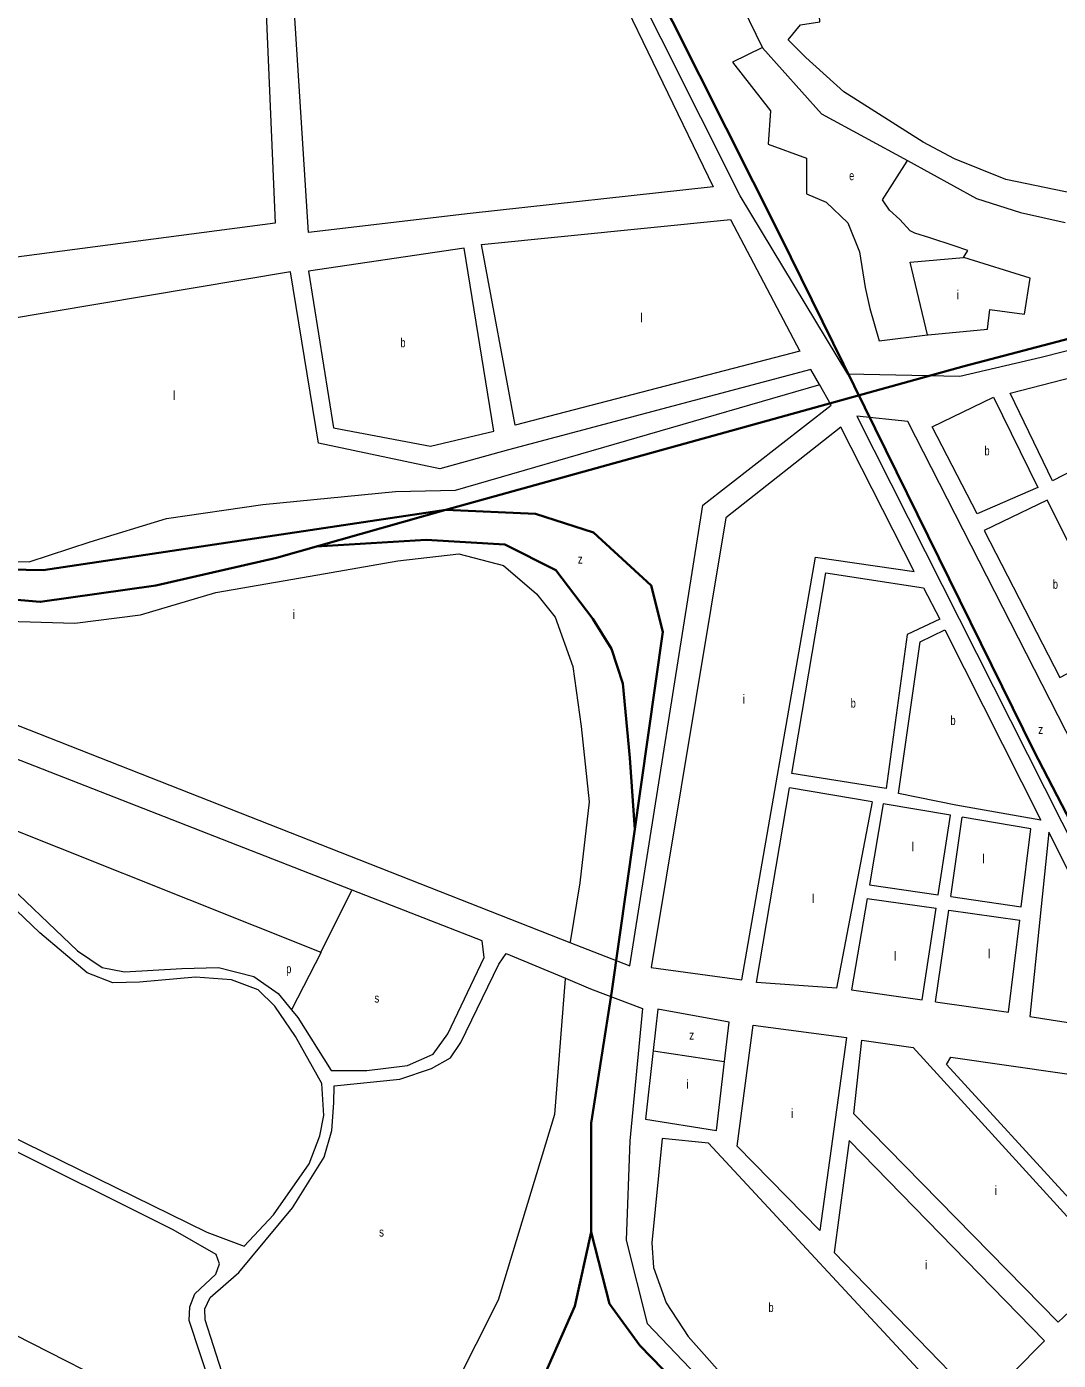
# Model space of a CAD drawing. Extents: x 639657 to 671642, y 222838 to 252123.
# Drawn here: x 654734 to 655866, y 237316 to 238779 of the extents above; entities that cross this region are included whole.
import ezdxf

# ---------------------------------------------------------------- set-up
doc = ezdxf.new("R2010")
doc.units = 0
doc.header["$LTSCALE"] = 4
for name, color, linetype, lineweight in [('1', 7, 'Continuous', 13), ('21', 7, 'Continuous', 13), ('57', 7, 'Continuous', 35)]:
    doc.layers.add(name, color=color, linetype=linetype, lineweight=lineweight)
doc.layers.add('7', color=7, linetype='Continuous')

msp = doc.modelspace()

# ---------------------------------------------------------------- linework, layer by layer
at = {"layer": '1'}
for p, q in [((655573.543, 237959.93), (655610.77, 238179.7)), ((655677.028, 237943.286), (655573.543, 237959.93)), ((655661.614, 237928.754), (655570.866, 237944.123)), ((655734.136, 237826.789), (655747.502, 237914.018)), ((655747.735, 237824.798), (655760.41, 237911.854)), ((655233.82, 237776.3), (655091.058, 237832.008)), ((655658.718, 237837.833), (655734.136, 237826.789)), ((655656.148, 237822.707), (655639.12, 237722.47)), ((655656.148, 237822.707), (655731.866, 237811.973)), ((655747.735, 237824.798), (655825.198, 237813.453)), ((655716.465, 237711.459), (655731.866, 237811.973)), ((655730.933, 237709.399), (655745.585, 237810.028)), ((655745.585, 237810.028), (655823.446, 237798.99)), ((655639.12, 237722.47), (655716.465, 237711.459)), ((655426.45, 237701.43), (655421.307, 237655.861))]:
    msp.add_line(p, q, dxfattribs=at)
for points in [[(655757.79, 238394.89), (655635, 238397.56), (655516.94, 238593.09), (655387.1, 238851.85), (655218.68, 239196.07), (655116.33, 239399.32), (655031.02, 239566.46), (655002.45, 239634.53), (655028.09, 239640.54), (655070.34, 239648.57), (655090.41, 239641.01), (655108.51, 239626.42), (655128.77, 239589.85), (655166.65, 239514.49), (655216.84, 239420.09), (655541.27, 238755.5)], [(656718.907, 238780.019), (656625.27, 238774.66), (656525.23, 238756.25), (656405.61, 238726.41), (656315.33, 238704.82), (656225.69, 238679.49), (656149.4, 238649.6), (656114.03, 238632.12), (656063.82, 238641.61), (656057.49, 238615.66), (655994.43, 238601.74), (655937.14, 238593.33), (655873.63, 238597.66), (655808.27, 238611.08), (655751.82, 238633.86), (655717.51, 238651.81), (655630.69, 238707.14), (655588.91, 238744.79), (655569.62, 238764.19), (655583.18, 238780.65), (655604.36, 238783.92), (655596.58, 238911.02)], [(655541.27, 238755.5), (655605.91, 238683.22), (655700.291, 238631.718)], [(655700.291, 238631.718), (655776.01, 238590.4), (655824.22, 238574.94), (655873.4, 238563.8)], [(655187.53, 238293.76), (655054.44, 238321.79), (655023.58, 238509.9), (654655.16, 238448.15), (654651, 238265.87), (654629.499, 238213.197), (654604.311, 238151.491)], [(655972.49, 238447.52), (655847, 238415.92), (655757.79, 238394.89)], [(655603.686, 238386.179), (655594.24, 238402.65), (655262.68, 238314.59), (655187.53, 238293.76)], [(655330.132, 237774.561), (655395.96, 237748.72), (655475.98, 238254.09), (655616.72, 238363.45), (655603.686, 238386.179)], [(655610.77, 238179.7), (655717.79, 238163.28), (655735.84, 238128.82), (655699.86, 238112.23), (655677.028, 237943.286)], [(654604.311, 238151.491), (654571.94, 238072.19), (655330.132, 237774.561)], [(655091.058, 237832.008), (654562.24, 238038.36), (654553.18, 238035.45), (654512.29, 237952.25), (654512.66, 237937.22), (654526.22, 237910.7), (654538.18, 237905.09), (654607.66, 237897.69)], [(655661.614, 237928.754), (655622.41, 237724.32), (655534.7, 237730.62), (655570.866, 237944.123)], [(655747.502, 237914.018), (655673.76, 237926.38), (655658.718, 237837.833)], [(655825.198, 237813.453), (655835.59, 237899.25), (655760.41, 237911.854)], [(654607.66, 237897.69), (654631.51, 237889.15), (654666.31, 237872.29), (654700.71, 237850.05), (654789.85, 237765.25), (654817.17, 237747.13), (654841.46, 237742.36), (654904.21, 237746.07), (654944.48, 237747.08), (654983.4, 237737.3), (655010.19, 237718.63), (655024.83, 237700.799)], [(654691.45, 237574.71), (654931.87, 237456.7), (654972.69, 237441.44), (655004.99, 237475.71), (655043.95, 237531.63), (655055.6, 237562.57), (655060.12, 237584.7), (655057.78, 237619.91), (655029.1, 237671.3), (655006.24, 237704.57), (654988.07, 237722.38), (654958.78, 237733.47), (654919.5, 237736.53), (654857.86, 237730.95), (654828.87, 237730.23), (654800.66, 237741.35), (654748.53, 237785.17), (654689.1, 237841.7)], [(655730.933, 237709.399), (655811.21, 237697.97), (655823.446, 237798.99)], [(655024.83, 237700.799), (655031.8, 237692.31), (655068.29, 237633.96), (655107.38, 237634.03), (655151.83, 237639.44), (655179.99, 237651.96), (655196.08, 237674.38), (655235.88, 237758.09), (655233.82, 237776.3)], [(655128.869, 237139.406), (654971.76, 237216.77), (654979.59, 237226.1), (654975.91, 237244.28), (654966.71, 237246.73), (654930, 237360.78), (654929.65, 237372.73), (654935.3, 237385.09), (654966.84, 237412.74), (655025.88, 237483.56), (655060.37, 237539.17), (655068.76, 237568.39), (655071.23, 237598.54), (655071.3, 237617.34), (655143.64, 237624.52), (655178.27, 237636.13), (655198.93, 237647.93), (655210.32, 237664.87), (655252.22, 237750.8), (655259.99, 237762.27), (655325.088, 237735.267)], [(655325.088, 237735.267), (655352.83, 237723.76), (655409.78, 237702.09), (655395.78, 237557.04), (655391.93, 237448.21), (655414.69, 237356.56), (655633.75, 237127.48)], [(655499.747, 237644.013), (655504.71, 237687.27), (655426.45, 237701.43)], [(655421.307, 237655.861), (655412.83, 237580.75), (655491.05, 237568.2), (655499.747, 237644.013)]]:
    msp.add_lwpolyline(points, dxfattribs=at)
for points in [[(655321.66, 238945.55), (655487.32, 238603.19), (655220.8, 238573.91), (655043.17, 238552.93), (655001.02, 239218.6), (655171.2, 239246.48)], [(654978.88, 239211.77), (655006.9, 238563.25), (654653.18, 238516.81), (654662.52, 238830.84), (654668.1, 239166.26)], [(655232.94, 238539.82), (655506.31, 238567.03), (655582.19, 238422.66), (655270.2, 238341.86)], [(655177.21, 238318.67), (655246.52, 238335.17), (655214.24, 238535.59), (655043.17, 238510.66), (655070.85, 238338.59)], [(655859.35, 238280.68), (655812.89, 238376.75), (655940.78, 238409.79), (655974.43, 238339.95)], [(655776.9, 238244.6), (655727.34, 238339.7), (655794.74, 238372.54), (655843.42, 238273.3)], [(655644.769, 238351.536), (655981.971, 237684.267), (655999.696, 237676.665), (656047.807, 237666.529), (655700.903, 238345.623)], [(655419.34, 237747.08), (655518.52, 237733.44), (655599.32, 238197.07), (655707.67, 238181.29), (655627.43, 238339.36), (655501, 238240.07)], [(655933.71, 238099.9), (655853.43, 238259.58), (655784.43, 238226.17), (655867.44, 238064.95)], [(655714.44, 238104.11), (655741.18, 238117.34), (655846.64, 237908.66), (655753.37, 237925.17), (655690.41, 237937.78)], [(655834.51, 237693.3), (655949.34, 237675.4), (655959.76, 237688.37), (655855.55, 237895.39)], [(655633.44, 237670.23), (655604.3, 237458.52), (655513.41, 237551.22), (655531.04, 237683.79)], [(655927.63, 237416.82), (655865.71, 237358.16), (655641.45, 237586.63), (655650.17, 237667.42), (655706.78, 237659.16)], [(655747.86, 237648.91), (655994.78, 237613.16), (656001.01, 237600.42), (655881.85, 237489.49), (655743.23, 237640.73)], [(654627.3, 237392.18), (654946.15, 237229.85), (654950.04, 237246.06), (654912.27, 237360.07), (654913.29, 237374.94), (654918.52, 237389.23), (654941.62, 237410.75), (654945.63, 237422.13), (654942.15, 237432.25), (654894.85, 237459.45), (654697.28, 237557.76), (654682.1, 237563.29), (654667.02, 237565.06), (654649.89, 237562.48), (654496.77, 237516.88), (654463.4, 237519.26), (654418.52, 237535.24), (654379.14, 237563.26), (654314.56, 237546.61), (654479.4, 237463.7)], [(655730.21, 237286.76), (655482.26, 237554.55), (655431.09, 237559.72), (655420, 237445.01), (655421.75, 237418.19), (655435.62, 237379.32), (655459.65, 237342.32), (655512.17, 237283.46), (655611.28, 237178.99)], [(655620.01, 237434.63), (655781.57, 237267.83), (655850.73, 237337.77), (655636.27, 237557.5)]]:
    msp.add_lwpolyline(points, close=True, dxfattribs=at)
at = {"layer": '21'}
for points in [[(655541.27, 238755.5), (655540.77, 238755.258), (655508.46, 238739.647), (655550.24, 238686.434), (655547.708, 238649.692), (655589.488, 238634.489), (655589.488, 238595.213), (655611.012, 238586.345), (655635.067, 238563.54), (655647.728, 238531.865), (655654.058, 238492.59), (655659.122, 238469.784), (655669.251, 238434.309), (655722.426, 238440.644)], [(655761.674, 238525.531), (655766.738, 238533.132), (655751.545, 238538.2), (655724.958, 238547.069), (655708.499, 238552.137), (655703.435, 238554.671), (655692.04, 238567.341), (655680.645, 238577.476), (655673.049, 238588.879), (655699.973, 238631.218), (655700.291, 238631.718)], [(655722.426, 238440.644), (655703.435, 238520.463), (655761.674, 238525.531)], [(655722.426, 238440.644), (655722.926, 238440.692), (655788.262, 238446.979), (655790.794, 238468.517), (655828.776, 238463.449), (655835.106, 238502.725), (655762.174, 238525.376), (655761.674, 238525.531)], [(654629.499, 238213.197), (654629.999, 238213.053), (654699.447, 238193.006), (654736.807, 238191.717), (654803.795, 238213.632), (654887.531, 238239.416), (654993.168, 238254.885), (655138.74, 238269.066), (655204.44, 238270.355), (655603.186, 238386.034), (655603.686, 238386.179)], [(654604.311, 238151.491), (654604.811, 238151.351), (654640.187, 238141.439), (654700.735, 238127.259), (654787.047, 238124.68), (654859.189, 238133.704), (654941.637, 238158.198), (655053.714, 238177.536), (655141.315, 238193.006), (655208.304, 238200.741), (655257.258, 238187.849), (655293.328, 238156.909), (655313.94, 238131.126), (655333.264, 238076.981), (655342.282, 238011.234), (655351.3, 237928.728), (655340.994, 237839.776), (655330.215, 237775.061), (655330.132, 237774.561)], [(654607.66, 237897.69), (654607.872, 237898.19), (654624.085, 237936.465), (655056.936, 237763.718)], [(655056.936, 237763.718), (655090.808, 237831.508), (655091.058, 237832.008)], [(655056.936, 237763.718), (655056.681, 237763.218), (655025.085, 237701.299), (655024.83, 237700.799)], [(655325.088, 237735.267), (655325.049, 237734.767), (655313.298, 237585.814), (655251.462, 237382.127), (655129.122, 237139.906), (655128.869, 237139.406)], [(655421.307, 237655.861), (655421.807, 237655.785), (655499.247, 237644.089), (655499.747, 237644.013)]]:
    msp.add_lwpolyline(points, dxfattribs=at)
at = {"layer": '57'}
for points in [[(654797.19, 240000.437), (654933.303, 239778.678), (655058.597, 239547.552), (655560.75, 238549.596)], [(654002.119, 239034.206), (654070.566, 238864.887), (654144.193, 238697.237), (654202.587, 238585.471), (654273.675, 238478.785), (654332.069, 238397.5), (654423.469, 238313.675), (654563.107, 238227.31), (654677.356, 238184.128), (654752.252, 238182.858), (655194.015, 238248.902), (655762.722, 238406.391), (656798.58, 238678.186), (656935.679, 238718.829), (657164.177, 238739.15), (657282.235, 238750.582), (657411.717, 238748.041), (657640.216, 238725.18), (658021.046, 238692.158), (658135.295, 238681.998), (658828.406, 238524.508), (660845.547, 238106.667)], [(655560.75, 238549.596), (655838.888, 237984.728), (656510.419, 236690.524), (656703.373, 236261.239), (656797.311, 236068.188), (656835.394, 236007.224)], [(653998.382, 238348.575), (654337.784, 238274.941), (654411.411, 238249.54), (654538.354, 238198.737), (654660.22, 238155.555), (654749.081, 238147.934), (654876.024, 238165.715), (655008.045, 238196.197), (655194.015, 238248.902)], [(655194.015, 238248.902), (655292.399, 238244.46), (655355.87, 238224.139), (655419.342, 238165.715), (655432.037, 238114.912), (655376.181, 237721.189), (655353.332, 237576.401), (655353.332, 237457.014), (655373.643, 237378.269), (655406.648, 237332.547), (655597.063, 237136.955), (656008.36, 236697.51), (656070.563, 236632.736), (656288.906, 236411.743), (656545.331, 236205.991), (656771.291, 236025.64), (656852.535, 235959.596), (656992.172, 235863.071), (657124.194, 235784.326), (657157.833, 235765.91), (657427.225, 235685.806)], [(655051.67, 238208.56), (655172.438, 238215.883), (655258.759, 238210.803), (655314.614, 238182.861), (655355.236, 238129.518), (655375.547, 238096.496), (655388.242, 238058.394), (655395.858, 237977.109), (655401.296, 237898.222)], [(655353.332, 237457.014), (655335.56, 237375.729), (655297.477, 237289.364), (655228.927, 237192.838), (655152.761, 237078.531), (655038.512, 236938.823), (654939.496, 236847.378), (654825.247, 236771.173), (654683.07, 236684.808), (654548.51, 236613.684), (654442.513, 236566.057), (654386.657, 236538.115), (654205.128, 236445.4), (653995.671, 236346.334)]]:
    msp.add_lwpolyline(points, dxfattribs=at)

# ---------------------------------------------------------------- texts
at = {"layer": '7'}
for s, width, p in [('e', 0.75, (655636.406, 238610.282)), ('b', 0.75, (655144.158, 238427.13)), ('b', 0.75, (655784.841, 238308.57)), ('z', 0.8, (655338.783, 238189.901)), ('b', 0.75, (655859.845, 238162.265)), ('b', 0.75, (655638.087, 238031.938)), ('b', 0.75, (655747.594, 238013)), ('z', 0.8, (655843.814, 238003.089)), ('p', 0.75, (655018.959, 237740.762)), ('s', 0.8, (655115.577, 237708.533)), ('z', 0.8, (655460.99, 237667.882)), ('s', 0.8, (655120.73, 237451.99)), ('b', 0.75, (655547.913, 237369.355))]:
    msp.add_text(s, height=10, dxfattribs=dict(at, width=width)).set_placement(p)
for s, p in [('i', (655754.15, 238479.785)), ('l', (655407.247, 238454.445)), ('l', (654894.525, 238369.361)), ('i', (655025.739, 238129.31)), ('i', (655519.291, 238036.4)), ('l', (655704.833, 237874.324)), ('l', (655782.128, 237861.432)), ('l', (655595.332, 237817.601)), ('l', (655685.509, 237754.432)), ('l', (655788.569, 237757.011)), ('i', (655457.475, 237614.07)), ('i', (655572.415, 237582.12)), ('i', (655795.909, 237497.771)), ('i', (655719.283, 237415.978))]:
    msp.add_text(s, height=10, dxfattribs=at).set_placement(p)

doc.saveas('drawing.dxf')
